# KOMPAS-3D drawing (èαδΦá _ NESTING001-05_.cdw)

Views: Спереди 1, Спереди, Проекционный вид 2
Referenced files in \\Smallatom\скворечник\: Крыша.m3d, Крыша _ NESTING001-05.cdw
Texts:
  NESTING001-05
  Крыша
  *- размер для справки.
  Лит-Масса-Масштаб
  Материал-Предприятие
  Title Specification
  Body Specification ( left align )
  Body Specificaton ( centered )
  Поз.
  Кол.
  Приме-
  чание
  Таблица спецификации
  NESTING001-05-
  Демьянова Л.В.
  КЮТ СО РАН
Dimensions and other numbers on the sheet: 178,37; 240; 15; 6; 1:2; 1; 0,98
